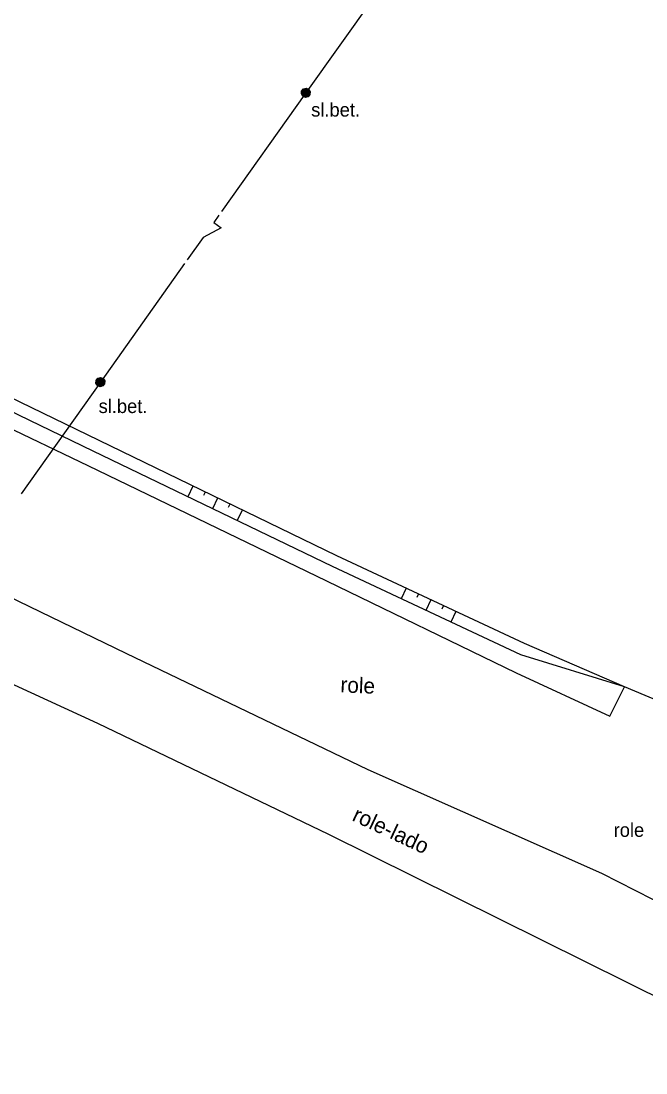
# Model space of a CAD drawing. Extents: x -661586 to -658793, y -1053889 to -1051031.
# Drawn here: x -659842.1 to -659705.3, y -1052572.1 to -1052341.9 of the extents above; entities that cross this region are included whole.
import ezdxf

# ---------------------------------------------------------------- set-up
doc = ezdxf.new("R2010")
doc.units = 0
for name, color, linetype in [('Vrstva 50', 7, 'Continuous'), ('Vrstva 51', 7, 'Continuous'), ('Vrstva 52', 7, 'Continuous'), ('Vrstva 53', 7, 'Continuous'), ('Vrstva 54', 7, 'Continuous')]:
    doc.layers.add(name, color=color, linetype=linetype)

msp = doc.modelspace()

# ---------------------------------------------------------------- linework, layer by layer
at = {"layer": 'Vrstva 51'}
for p, q in [((-659761.41, -1052331.848), (-659779.749, -1052357.603)), ((-659779.749, -1052357.603), (-659798.179, -1052383.547)), ((-659806.287, -1052394.96), (-659824.718, -1052420.904)), ((-659824.718, -1052420.904), (-659842.046, -1052445.377))]:
    msp.add_line(p, q, dxfattribs=at)
for points in [[(-659780.727, -1052357.837), (-659780.685, -1052357.219), (-659780.292, -1052356.744), (-659779.7, -1052356.584), (-659779.134, -1052356.823), (-659778.809, -1052357.346), (-659778.851, -1052357.965), (-659779.244, -1052358.439), (-659779.836, -1052358.599), (-659780.402, -1052358.36), (-659780.727, -1052357.837), (-659780.643, -1052357.783), (-659780.61, -1052357.304), (-659780.429, -1052356.995), (-659780.505, -1052358.113), (-659780.356, -1052358.283), (-659780.259, -1052356.847), (-659780.099, -1052356.858), (-659780.197, -1052358.294), (-659780.042, -1052358.385), (-659779.934, -1052356.789), (-659779.769, -1052356.72), (-659779.888, -1052358.476), (-659779.729, -1052358.486), (-659779.609, -1052356.73), (-659779.454, -1052356.801), (-659779.564, -1052358.417), (-659779.403, -1052358.408), (-659779.293, -1052356.792), (-659779.14, -1052356.903), (-659779.237, -1052358.339), (-659779.067, -1052358.191), (-659778.991, -1052357.073), (-659778.846, -1052357.303), (-659778.892, -1052357.982)], [(-659798.76, -1052384.361), (-659799.918, -1052385.992), (-659798.287, -1052387.15), (-659802.233, -1052389.253), (-659805.707, -1052394.146)], [(-659825.696, -1052421.138), (-659825.654, -1052420.519), (-659825.261, -1052420.045), (-659824.668, -1052419.885), (-659824.103, -1052420.124), (-659823.778, -1052420.647), (-659823.82, -1052421.265), (-659824.213, -1052421.74), (-659824.805, -1052421.9), (-659825.37, -1052421.661), (-659825.696, -1052421.138), (-659825.612, -1052421.084), (-659825.579, -1052420.605), (-659825.398, -1052420.296), (-659825.474, -1052421.414), (-659825.325, -1052421.584), (-659825.228, -1052420.147), (-659825.068, -1052420.158), (-659825.165, -1052421.595), (-659825.011, -1052421.686), (-659824.903, -1052420.089), (-659824.738, -1052420.02), (-659824.857, -1052421.776), (-659824.697, -1052421.787), (-659824.578, -1052420.031), (-659824.423, -1052420.102), (-659824.532, -1052421.718), (-659824.371, -1052421.709), (-659824.262, -1052420.093), (-659824.109, -1052420.203), (-659824.206, -1052421.64), (-659824.036, -1052421.491), (-659823.96, -1052420.374), (-659823.815, -1052420.604), (-659823.861, -1052421.283)]]:
    msp.add_lwpolyline(points, dxfattribs=at)
at = {"layer": 'Vrstva 53'}
for p, q in [((-659919.22, -1052395.39), (-659827.49, -1052439.12)), ((-659772.99, -1052458.92), (-659875.15, -1052409.4)), ((-659819.11, -1052480.26), (-659903.22, -1052439.69)), ((-659827.49, -1052439.12), (-659775.19, -1052464.36)), ((-659731.84, -1052478.09), (-659772.99, -1052458.92)), ((-659896.84, -1052462.65), (-659825.32, -1052495.54)), ((-659775.19, -1052464.36), (-659733.73, -1052484.53)), ((-659709.967, -1052487.601), (-659731.84, -1052478.09)), ((-659766.09, -1052505.728), (-659819.11, -1052480.26)), ((-659733.73, -1052484.53), (-659713.156, -1052494.003)), ((-659713.156, -1052494.003), (-659709.967, -1052487.601)), ((-659682.805, -1052498.99), (-659709.967, -1052487.601)), ((-659825.32, -1052495.54), (-659774.776, -1052519.836)), ((-659714.978, -1052528.47), (-659766.09, -1052505.728)), ((-659774.776, -1052519.836), (-659698.215, -1052557.835)), ((-659628.851, -1052572.089), (-659714.978, -1052528.47))]:
    msp.add_line(p, q, dxfattribs=at)
at = {"layer": 'Vrstva 54'}
for p, q in [((-659826.33, -1052436.02), (-659876.01, -1052411.98)), ((-659773.93, -1052461.25), (-659826.33, -1052436.02)), ((-659804.479, -1052443.656), (-659805.613, -1052445.995)), ((-659801.78, -1052444.965), (-659802.156, -1052445.741)), ((-659799.08, -1052446.273), (-659800.207, -1052448.598)), ((-659796.38, -1052447.582), (-659796.754, -1052448.354)), ((-659793.681, -1052448.891), (-659794.801, -1052451.201)), ((-659732.68, -1052480.59), (-659773.93, -1052461.25)), ((-659757.794, -1052465.999), (-659758.871, -1052468.31)), ((-659755.075, -1052467.266), (-659755.434, -1052468.038)), ((-659752.355, -1052468.533), (-659753.438, -1052470.858)), ((-659749.636, -1052469.8), (-659749.998, -1052470.576)), ((-659746.916, -1052471.067), (-659748.006, -1052473.405)), ((-659709.967, -1052487.601), (-659732.68, -1052480.59))]:
    msp.add_line(p, q, dxfattribs=at)

# ---------------------------------------------------------------- texts
at = {"layer": 'Vrstva 50'}
for p in [(-659778.578, -1052362.798), (-659825.117, -1052427.67)]:
    msp.add_text('sl.bet.', height=3, dxfattribs=at).set_placement(p)
at = {"layer": 'Vrstva 52'}
msp.add_text('role', height=3, dxfattribs=at).set_placement((-659712.358, -1052520.415))
at = {"layer": 'Vrstva 53'}
for s, rotation, p in [('role', 357.58296, (-659772.235, -1052488.786)), ('role-lado', 334.83654, (-659769.832, -1052516.761))]:
    msp.add_text(s, height=3.4, rotation=rotation, dxfattribs=at).set_placement(p)

doc.saveas('drawing.dxf')
